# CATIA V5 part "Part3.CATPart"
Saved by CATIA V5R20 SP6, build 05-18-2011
Part number: Velt
Material "Rubber": density 910 kg/m3, Young's modulus 2e+06 Pa, Poisson ratio 0.49, thermal expansion 0.000162 1/K
Bounding box of the stored display mesh (mm): x -591.5 to -571.5, y 29.75 to 286.25, z -486 to 24.25
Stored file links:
  E:\#01 CATIA Lecture Materials\#06 DMU\#11 DMU Page01 KIN EX11\Part3.CATPart
  C:\Program Files\Dassault Systemes\B20\win_b64\startup\materials\Catalog.CATMaterial
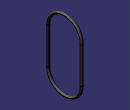
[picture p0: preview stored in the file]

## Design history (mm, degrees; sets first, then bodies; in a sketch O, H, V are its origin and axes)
Body1 (main body)
  Plane1: type Offset, RefPlane zx-plane, Offset 158
  Sketch1 on Plane1, origin (0, 158, 0), H (-1, 0, 0), V (0, 0, 1)
    circle A1 centre (581.5, 14.25) radius 10
    point P1 (581.5, 14.25)
    distance P1 V = 581.5
    distance P1 H = 14.25
    radius A1 = 10
  Plane2: type Offset, RefPlane yz-plane, Offset 581.5, reversed
  DatumCurve1
  DatumCurve2
  Sketch2 on Plane2, origin (-581.5, 0, 0), H (0, 1, 0), V (0, 0, 1)
    construction line L1 (158, -104) -> (158, -357.75)
    point P1 (158, -104)
    point P2 (158, -357.75)
    line L2 (276.25, -104) -> (276.25, -357.75)
    line L3 (39.75, -357.75) -> (39.75, -104)
    arc A1 centre (158, -357.75) radius 118.25 from (276.25, -357.75) to (39.75, -357.75) cw
    arc A2 centre (158, -104) radius 118.25 from (39.75, -104) to (276.25, -104) cw
    reference projected circle E1 centre (158, -357.75) radius 111.2454 from edge of DatumCurve1
    reference projected circle E2 centre (158, -104) radius 111.2454 from edge of DatumCurve2
    distance A2 H = 14.25
    radius A1 = 118.25
    tangency: A1 L2, A2 L2, A1 L3, A2 L3
    concentricity: P2 E1, P1 E2
  Rib1: profile Sketch1, centre curve Sketch2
